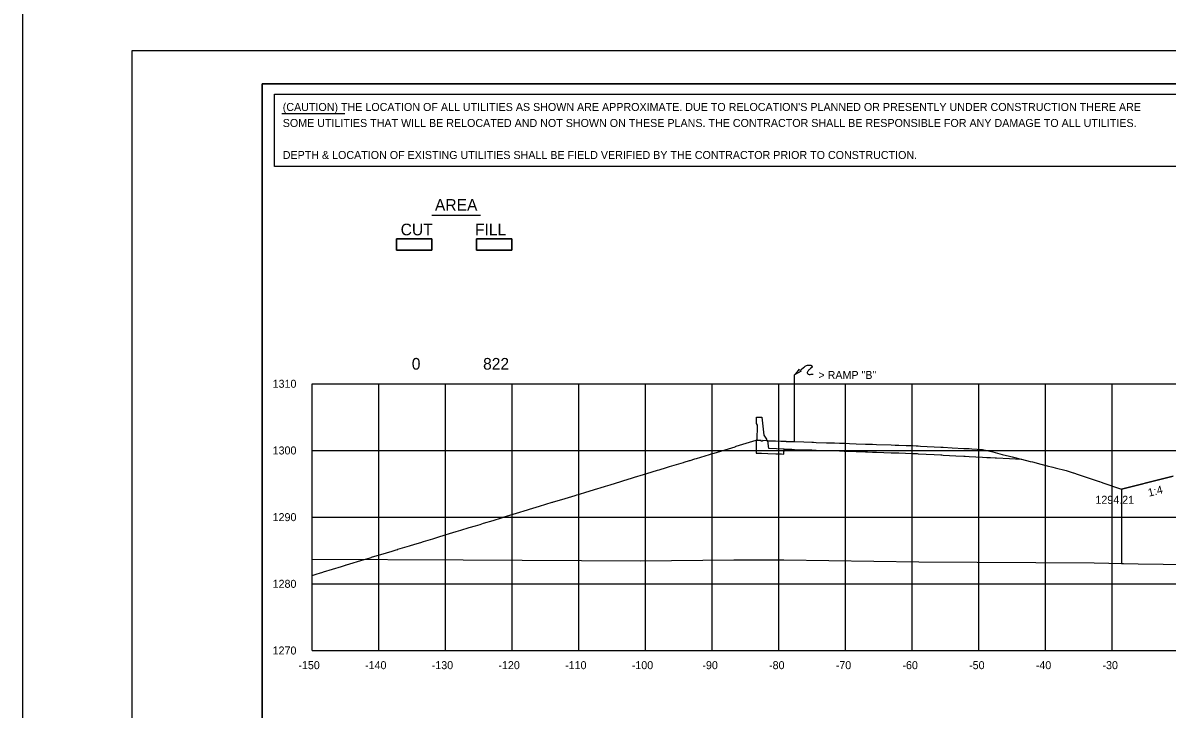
# Model space of a CAD drawing. Extents: x 2148105 to 2149976, y 144169 to 149705.
# Drawn here: x 2148219.9 to 2148391.5, y 145038.1 to 145141 of the extents above; entities that cross this region are included whole.
import ezdxf

# ---------------------------------------------------------------- set-up
doc = ezdxf.new("R2010")
doc.units = 0
for name, color, linetype in [('EX_Align', 7, 'Continuous'), ('INR_Tracking', 7, 'Continuous'), ('PH1a-2-RampC', 7, 'Continuous'), ('PH1a-PR-DividingStrip', 7, 'Continuous'), ('PH1a-PR-ServRd', 7, 'Continuous'), ('PR-Dividing Strip', 7, 'Continuous'), ('PR_Align_PC', 7, 'Continuous'), ('PR_Align_PI', 7, 'Continuous'), ('PR_Align_Ramp_E', 7, 'Continuous'), ('PR_Align_Ramp_J', 7, 'Continuous'), ('PR_Storm_Conc_Box_PH1B', 7, 'Continuous'), ('PR_Storm_Conc_Pipe_PH1B', 7, 'Continuous'), ('PR_Storm_Inlet_CICI_PH1A', 7, 'Continuous'), ('PR_Storm_Inlet_CICI_PH1B', 7, 'Continuous'), ('PR_Storm_MH', 7, 'Continuous'), ('PR_Storm_MH_PH1B', 7, 'Continuous'), ('PR_Storm_Standard_Median_Drain_PH1B', 7, 'Continuous'), ('TopCut', 7, 'Continuous'), ('TOPO_BRIDGE_Pier Cap', 7, 'Continuous')]:
    doc.layers.add(name, color=color, linetype=linetype)

msp = doc.modelspace()

# ---------------------------------------------------------------- linework, layer by layer
at = {"layer": 'EX_Align'}
msp.add_lwpolyline([(2148263.32, 145058.18), (2148264.07, 145058.41), (2148264.45, 145058.52), (2148264.95, 145058.67), (2148265.03, 145058.7), (2148267.75, 145059.52), (2148268.34, 145059.71), (2148268.44, 145059.74), (2148268.46, 145059.74), (2148271.13, 145060.55), (2148271.89, 145060.78), (2148272.16, 145060.87), (2148272.24, 145060.89), (2148274.5, 145061.58), (2148275.32, 145061.83), (2148275.91, 145062), (2148276.14, 145062.08), (2148276.14, 145062.08), (2148276.17, 145062.08), (2148276.17, 145062.08), (2148276.18, 145062.09), (2148277.95, 145062.63), (2148278.75, 145062.87), (2148279.61, 145063.13), (2148280.03, 145063.26), (2148281.42, 145063.68), (2148282.18, 145063.91), (2148283.27, 145064.24), (2148283.93, 145064.44), (2148284.94, 145064.75), (2148285.61, 145064.95), (2148286.89, 145065.34), (2148287.83, 145065.63), (2148288.5, 145065.83), (2148289.04, 145066), (2148290.46, 145066.43), (2148291.73, 145066.81), (2148292.1, 145066.93), (2148292.47, 145067.04), (2148293.99, 145067.5), (2148295.62, 145068), (2148295.75, 145068.04), (2148295.9, 145068.08), (2148297.4, 145068.54), (2148299.33, 145069.13), (2148299.41, 145069.15), (2148299.52, 145069.19), (2148300.79, 145069.57), (2148302.76, 145070.17), (2148303, 145070.24), (2148303.42, 145070.37), (2148304.37, 145070.66), (2148306.19, 145071.21), (2148306.54, 145071.32), (2148307.31, 145071.56), (2148308, 145071.76), (2148309.62, 145072.26), (2148310.05, 145072.39), (2148311.21, 145072.74), (2148311.67, 145072.88), (2148313.04, 145073.3), (2148313.51, 145073.44), (2148315.11, 145073.93), (2148315.38, 145074.01), (2148316.47, 145074.34), (2148316.92, 145074.48), (2148319.01, 145075.11), (2148319.14, 145075.15), (2148319.9, 145075.39), (2148320.02, 145075.42), (2148320.73, 145075.64), (2148320.99, 145075.72), (2148322.9, 145076.3), (2148322.94, 145076.31), (2148323.33, 145076.43), (2148323.63, 145076.52), (2148326.76, 145077.47), (2148326.76, 145077.47), (2148326.8, 145077.48), (2148326.94, 145077.53), (2148329.9, 145078.43), (2148329.91, 145077.36), (2148329.91, 145077.26), (2148329.92, 145076.57), (2148329.92, 145076.51), (2148330.19, 145076.5), (2148330.52, 145076.49), (2148330.7, 145076.48), (2148331.65, 145076.45), (2148333.62, 145076.39), (2148333.73, 145076.38), (2148334.08, 145076.37), (2148334.08, 145076.64), (2148334.09, 145077.12), (2148334.26, 145077.11), (2148334.34, 145077.11), (2148334.39, 145077.11), (2148334.59, 145077.1), (2148335.24, 145077.08), (2148335.65, 145077.07), (2148336.86, 145077.02), (2148337.05, 145077.02), (2148338.25, 145076.98), (2148338.49, 145076.97), (2148338.9, 145076.96), (2148340.48, 145076.9), (2148341.15, 145076.88), (2148342.39, 145076.84), (2148343.11, 145076.81), (2148343.91, 145076.78), (2148344.89, 145076.75), (2148346.29, 145076.7), (2148346.6, 145076.69), (2148347.34, 145076.67), (2148347.95, 145076.65), (2148350.18, 145076.57), (2148350.75, 145076.55), (2148350.77, 145076.55), (2148351.33, 145076.53), (2148352.3, 145076.5), (2148353.42, 145076.46), (2148354.08, 145076.43), (2148354.19, 145076.42), (2148354.2, 145076.42), (2148356.59, 145076.29), (2148357.63, 145076.24), (2148357.77, 145076.23), (2148357.98, 145076.22), (2148359.88, 145076.12), (2148361.06, 145076.06), (2148361.26, 145076.04), (2148361.87, 145076.01), (2148363.88, 145075.91), (2148364.49, 145075.87), (2148365.05, 145075.84), (2148365.77, 145075.8), (2148365.97, 145075.79), (2148367.92, 145075.69), (2148369.65, 145075.6), (2148369.67, 145075.6), (2148369.67, 145075.6), (2148369.69, 145075.6), (2148371.01, 145075.26), (2148371.35, 145075.18), (2148372.6, 145074.86), (2148373.57, 145074.61), (2148374.41, 145074.4), (2148374.78, 145074.31), (2148376.42, 145073.89), (2148377.46, 145073.54), (2148377.48, 145073.53), (2148378.2, 145073.29), (2148378.34, 145073.25), (2148381.36, 145072.24), (2148381.39, 145072.23), (2148381.63, 145072.15), (2148382.07, 145072), (2148384.72, 145071.11)], dxfattribs=at)
at = {"layer": 'INR_Tracking'}
msp.add_lwpolyline([(2148384.72, 145071.11), (2148384.72, 145071.11), (2148391.45, 145072.8), (2148392.44, 145073.04)], dxfattribs=at)
at = {"layer": 'PH1a-PR-ServRd'}
msp.add_lwpolyline([(2148570.82, 144921.91), (2148255.82, 144921.91), (2148255.82, 145131.91), (2148570.82, 145131.91)], close=True, dxfattribs=at)
at = {"layer": 'PR-Dividing Strip'}
msp.add_line((2148335.65, 145078.23), (2148335.65, 145088.23), dxfattribs=at)
for points in [[(2148335.65, 145088.23), (2148336.17, 145088.78), (2148336.43, 145089.09), (2148336.51, 145088.92), (2148336.65, 145088.81), (2148335.65, 145088.23)], [(2148336.66, 145089.04), (2148337.01, 145089.34), (2148337.18, 145089.46), (2148337.27, 145089.54), (2148337.37, 145089.59), (2148337.47, 145089.64), (2148337.59, 145089.68), (2148337.72, 145089.71), (2148337.81, 145089.72), (2148337.9, 145089.72), (2148337.98, 145089.71), (2148338.05, 145089.7), (2148338.1, 145089.68), (2148338.16, 145089.66), (2148338.2, 145089.64), (2148338.24, 145089.6), (2148338.27, 145089.56), (2148338.3, 145089.5), (2148338.3, 145089.45), (2148338.29, 145089.41), (2148338.24, 145089.34), (2148338.05, 145089.18), (2148337.86, 145089.01), (2148337.78, 145088.94), (2148337.72, 145088.86), (2148337.66, 145088.77), (2148337.62, 145088.71), (2148337.58, 145088.62), (2148337.58, 145088.54), (2148337.6, 145088.46), (2148337.64, 145088.39), (2148337.69, 145088.35), (2148337.75, 145088.33), (2148337.86, 145088.31), (2148337.99, 145088.32), (2148338.15, 145088.34), (2148338.48, 145088.37)]]:
    msp.add_lwpolyline(points, dxfattribs=at)
at = {"layer": 'PR_Align_PC'}
msp.add_line((2148281.28, 145112.21), (2148288.56, 145112.21), dxfattribs=at)
for points in [[(2148275.98, 145108.66), (2148281.29, 145108.66), (2148281.29, 145106.97), (2148275.98, 145106.97)], [(2148275.98, 145108.66), (2148281.29, 145108.66), (2148281.29, 145106.97), (2148275.98, 145106.97)], [(2148287.98, 145108.66), (2148293.29, 145108.66), (2148293.29, 145106.97), (2148287.98, 145106.97)], [(2148287.98, 145108.66), (2148293.29, 145108.66), (2148293.29, 145106.97), (2148287.98, 145106.97)]]:
    msp.add_lwpolyline(points, close=True, dxfattribs=at)
at = {"layer": 'PR_Align_PI'}
msp.add_lwpolyline([(2148331.65, 145078.37), (2148332.79, 145078.33), (2148333.62, 145078.3), (2148334.05, 145078.29), (2148334.34, 145078.28), (2148334.42, 145078.27), (2148334.6, 145078.27), (2148335, 145078.26), (2148335.65, 145078.23), (2148337.05, 145078.19), (2148338.25, 145078.14), (2148338.49, 145078.14), (2148338.91, 145078.12), (2148340.48, 145078.07), (2148341.66, 145078.03), (2148342.39, 145078), (2148343.18, 145077.98), (2148343.91, 145077.95), (2148344.89, 145077.92), (2148346.29, 145077.87), (2148347.05, 145077.84), (2148347.34, 145077.83), (2148347.95, 145077.81), (2148350.18, 145077.74), (2148350.75, 145077.72), (2148350.77, 145077.72), (2148350.87, 145077.71), (2148351.33, 145077.7), (2148352.4, 145077.66), (2148353.42, 145077.63), (2148353.92, 145077.6), (2148354.08, 145077.59), (2148354.09, 145077.59), (2148354.2, 145077.59), (2148354.58, 145077.57), (2148357.63, 145077.4), (2148357.83, 145077.39), (2148357.98, 145077.38), (2148359.32, 145077.31), (2148361.06, 145077.22), (2148361.26, 145077.21), (2148361.88, 145077.18), (2148362.28, 145077.16), (2148363.88, 145077.07), (2148364.49, 145076.92), (2148365.43, 145076.68), (2148365.77, 145076.59), (2148366.83, 145076.32), (2148367.92, 145076.05), (2148368.33, 145075.94), (2148369.67, 145075.6), (2148369.69, 145075.6)], dxfattribs=at)
at = {"layer": 'PR_Align_Ramp_E'}
msp.add_lwpolyline([(2148219.95, 145145.16), (2148579.95, 145145.16), (2148579.95, 144905.16), (2148219.95, 144905.16)], close=True, dxfattribs=at)
at = {"layer": 'PR_Align_Ramp_J'}
msp.add_lwpolyline([(2148236.32, 145136.91), (2148576.32, 145136.91), (2148576.32, 144916.91), (2148236.32, 144916.91)], close=True, dxfattribs=at)
at = {"layer": 'PR_Storm_Conc_Box_PH1B'}
for p, q in [((2148263.32, 145086.91), (2148563.32, 145086.91)), ((2148263.32, 145046.91), (2148263.32, 145086.91)), ((2148273.32, 145046.91), (2148273.32, 145086.91)), ((2148283.32, 145046.91), (2148283.32, 145086.91)), ((2148293.32, 145046.91), (2148293.32, 145086.91)), ((2148303.32, 145046.91), (2148303.32, 145086.91)), ((2148313.32, 145046.91), (2148313.32, 145086.91)), ((2148323.32, 145046.91), (2148323.32, 145086.91)), ((2148333.32, 145046.91), (2148333.32, 145086.91)), ((2148343.32, 145046.91), (2148343.32, 145086.91)), ((2148353.32, 145046.91), (2148353.32, 145086.91)), ((2148363.32, 145046.91), (2148363.32, 145086.91)), ((2148373.32, 145046.91), (2148373.32, 145086.91)), ((2148383.32, 145046.91), (2148383.32, 145086.91)), ((2148263.32, 145076.91), (2148563.32, 145076.91)), ((2148263.32, 145066.91), (2148563.32, 145066.91)), ((2148263.32, 145056.91), (2148563.32, 145056.91)), ((2148263.32, 145046.91), (2148563.32, 145046.91))]:
    msp.add_line(p, q, dxfattribs=at)
at = {"layer": 'PR_Storm_Conc_Pipe_PH1B'}
msp.add_lwpolyline([(2148255.82, 144921.91), (2148570.82, 144921.91), (2148570.82, 145131.91), (2148255.82, 145131.91)], close=True, dxfattribs=at)
msp.add_lwpolyline([(2148255.82, 144921.91), (2148570.82, 144921.91), (2148570.82, 145131.91), (2148255.82, 145131.91)], close=True, dxfattribs=at)
at = {"layer": 'PR_Storm_Inlet_CICI_PH1A'}
for points in [[(2148330.09, 145078.42), (2148330.1, 145080.7), (2148329.97, 145080.97), (2148329.97, 145081.9), (2148330.75, 145081.88), (2148331.05, 145079.21), (2148331.46, 145078.62), (2148331.47, 145078.37), (2148330.86, 145078.39), (2148330.86, 145078.31), (2148330.68, 145078.32), (2148330.68, 145078.4)], [(2148330.09, 145078.42), (2148330.1, 145080.7), (2148329.97, 145080.97), (2148329.97, 145081.9), (2148330.75, 145081.88), (2148331.05, 145079.21), (2148331.46, 145078.62), (2148331.47, 145078.37), (2148330.86, 145078.39), (2148330.86, 145078.31), (2148330.68, 145078.32), (2148330.68, 145078.4)], [(2148329.92, 145076.51), (2148331.65, 145076.45), (2148334.08, 145076.37), (2148334.09, 145077.12), (2148331.82, 145077.2), (2148331.65, 145078.37), (2148331.47, 145078.37), (2148330.86, 145078.39), (2148330.86, 145078.31), (2148330.68, 145078.32), (2148330.68, 145078.4), (2148330.09, 145078.42), (2148329.9, 145078.43), (2148329.91, 145077.26)], [(2148329.92, 145076.51), (2148331.65, 145076.45), (2148334.08, 145076.37), (2148334.09, 145077.12), (2148331.82, 145077.2), (2148331.65, 145078.37), (2148331.47, 145078.37), (2148330.86, 145078.39), (2148330.86, 145078.31), (2148330.68, 145078.32), (2148330.68, 145078.4), (2148330.09, 145078.42), (2148329.9, 145078.43), (2148329.91, 145077.26)]]:
    msp.add_lwpolyline(points, close=True, dxfattribs=at)
at = {"layer": 'PR_Storm_Inlet_CICI_PH1B'}
msp.add_lwpolyline([(2148263.32, 145060.59), (2148285.98, 145060.51), (2148312.57, 145060.38), (2148326.58, 145060.51), (2148334.04, 145060.51), (2148354.29, 145060.2), (2148380.61, 145060.04), (2148387.2, 145059.91), (2148394.69, 145059.83)], dxfattribs=at)
at = {"layer": 'PR_Storm_MH'}
msp.add_line((2148258.8, 145127.46), (2148268.21, 145127.46), dxfattribs=at)
msp.add_lwpolyline([(2148257.69, 145130.34), (2148420.12, 145130.34), (2148420.12, 145119.47), (2148257.69, 145119.47)], close=True, dxfattribs=at)
at = {"layer": 'PR_Storm_Standard_Median_Drain_PH1B'}
for q in [(2148263.32, 145086.91), (2148563.32, 145046.91)]:
    msp.add_line((2148263.32, 145046.91), q, dxfattribs=at)
at = {"layer": 'TopCut'}
for points in [[(2148287.98, 145106.97), (2148293.29, 145106.97), (2148293.29, 145108.66), (2148287.98, 145108.66), (2148287.98, 145106.97)], [(2148392.44, 145073.04), (2148391.45, 145072.8), (2148384.72, 145071.11), (2148384.72, 145059.96), (2148387.2, 145059.91), (2148394.69, 145059.83)]]:
    msp.add_lwpolyline(points, dxfattribs=at)
at = {"layer": 'TOPO_BRIDGE_Pier Cap'}
msp.add_lwpolyline([(2148275.98, 145106.97), (2148281.29, 145106.97), (2148281.29, 145108.66), (2148275.98, 145108.66), (2148275.98, 145106.97)], dxfattribs=at)

# ---------------------------------------------------------------- texts
at = {"layer": 'PH1a-2-RampC'}
msp.add_text('1294.21', height=1.2, dxfattribs=at).set_placement((2148380.79, 145068.91))
at = {"layer": 'PH1a-PR-DividingStrip'}
msp.add_text('1:4', height=1.2, rotation=14.0361, dxfattribs=at).set_placement((2148388.83, 145069.97))
at = {"layer": 'PR-Dividing Strip'}
msp.add_text('> RAMP "B"', height=1.2, rotation=360, dxfattribs=at).set_placement((2148339.25, 145087.63))
at = {"layer": 'PR_Align_PC'}
for s, p in [('AREA', (2148281.74, 145112.86)), ('CUT', (2148276.6, 145109.17)), ('FILL', (2148287.74, 145109.17)), ('0', (2148278.27, 145089.03)), ('822', (2148288.96, 145089.03))]:
    msp.add_text(s, height=1.75, dxfattribs=at).set_placement(p)
at = {"layer": 'PR_Storm_MH'}
for s, p in [("(CAUTION) THE LOCATION OF ALL UTILITIES AS SHOWN ARE APPROXIMATE. DUE TO RELOCATION'S PLANNED OR PRESENTLY UNDER CONSTRUCTION THERE ARE ", (2148258.92, 145127.82)), ('SOME UTILITIES THAT WILL BE RELOCATED AND NOT SHOWN ON THESE PLANS. THE CONTRACTOR SHALL BE RESPONSIBLE FOR ANY DAMAGE TO ALL UTILITIES.', (2148258.92, 145125.42)), ('DEPTH & LOCATION OF EXISTING UTILITIES SHALL BE FIELD VERIFIED BY THE CONTRACTOR PRIOR TO CONSTRUCTION.', (2148258.92, 145120.62))]:
    msp.add_text(s, height=1.2, dxfattribs=at).set_placement(p)
at = {"layer": 'PR_Storm_MH_PH1B'}
for s, p in [('1310', (2148257.4, 145086.31)), ('1300', (2148257.4, 145076.31)), ('1290', (2148257.4, 145066.31)), ('1280', (2148257.4, 145056.31)), ('1270', (2148257.4, 145046.31)), ('-150', (2148261.26, 145044.11)), ('-140', (2148271.26, 145044.11)), ('-130', (2148281.26, 145044.11)), ('-120', (2148291.26, 145044.11)), ('-110', (2148301.26, 145044.11)), ('-100', (2148311.26, 145044.11)), ('-90', (2148321.85, 145044.11)), ('-80', (2148331.85, 145044.11)), ('-70', (2148341.85, 145044.11)), ('-60', (2148351.85, 145044.11)), ('-50', (2148361.85, 145044.11)), ('-40', (2148371.85, 145044.11)), ('-30', (2148381.85, 145044.11))]:
    msp.add_text(s, height=1.2, dxfattribs=at).set_placement(p)

doc.saveas('drawing.dxf')
